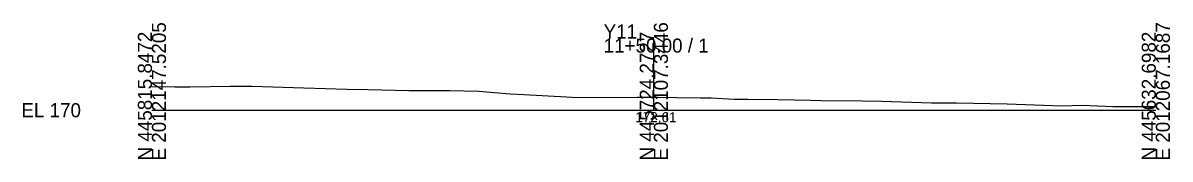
# Model space of a CAD drawing. Extents: x -26 to 203, y -10 to 3517.
# Drawn here: x -25.7 to 202.8, y 2990.3 to 3017.3 of the extents above; entities that cross this region are included whole.
import ezdxf

# ---------------------------------------------------------------- set-up
doc = ezdxf.new("R2010")
doc.units = 0
for name, color, linetype in [('Default', 7, 'Continuous'), ('Exist Cross Section Cell', 7, 'Continuous'), ('Exist XS Center Line Elevation Label', 7, 'Continuous'), ('Exist XS Ground Line', 7, 'Continuous')]:
    doc.layers.add(name, color=color, linetype=linetype)

msp = doc.modelspace()

# ---------------------------------------------------------------- linework, layer by layer
at = {"layer": 'Exist Cross Section Cell'}
for p, q in [((100, 3000), (100, 3014.24)), ((0, 3000), (100, 3000)), ((100, 3000), (200, 3000))]:
    msp.add_line(p, q, dxfattribs=at)
at = {"layer": 'Exist XS Ground Line'}
msp.add_lwpolyline([(0, 3004.71), (4.55, 3004.64), (7.64, 3004.63), (15.57, 3004.75), (19.95, 3004.75), (30.28, 3004.47), (38.88, 3004.19), (43.04, 3004.1), (51.21, 3003.94), (59.34, 3003.91), (65.12, 3003.8), (71.39, 3003.25), (74.07, 3003.15), (82.58, 3002.65), (83.66, 3002.6), (88.31, 3002.52), (96.68, 3002.62), (100, 3002.61), (100.85, 3002.61), (104.53, 3002.55), (109.26, 3002.47), (111.45, 3002.43), (116.03, 3002.17), (118.77, 3002.17), (124.7, 3002.13), (131.21, 3002), (133.31, 3001.96), (141.54, 3001.87), (145.36, 3001.78), (155.33, 3001.48), (160.31, 3001.47), (170.41, 3001.3), (181.29, 3000.9), (185.35, 3001.02), (191.43, 3000.76), (200, 3000.71)], dxfattribs=at)

# ---------------------------------------------------------------- texts
at = {"layer": 'Default'}
msp.add_text('-', height=0.0001, dxfattribs=at).set_placement((0, 3000))
at = {"layer": 'Exist Cross Section Cell'}
for s, p in [('E 2012147.5205', (2.8, 2990)), ('E 2012107.3446', (102.8, 2990)), ('E 2012067.1687', (202.8, 2990)), ('N 445815.8472', (0, 2990)), ('N 445724.2727', (100, 2990)), ('N 445632.6982', (200, 2990))]:
    msp.add_text(s, height=2.8, rotation=90, dxfattribs=at).set_placement(p)
for s, p in [('Y11', (90, 3014.24)), ('11+50.00 / 1', (90, 3011.44)), ('EL 170', (-26, 2998.6))]:
    msp.add_text(s, height=2.8, dxfattribs=at).set_placement(p)
at = {"layer": 'Exist XS Center Line Elevation Label'}
msp.add_text('172.61', height=2, dxfattribs=at).set_placement((96.32, 2997.61))

doc.saveas('drawing.dxf')
